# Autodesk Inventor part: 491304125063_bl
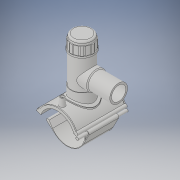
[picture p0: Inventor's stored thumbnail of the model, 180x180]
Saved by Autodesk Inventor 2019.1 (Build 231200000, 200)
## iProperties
Created: 2017-07
Part Number: 491304125063_bl
Material: Generic
Description: PLASSON TAPPING TEE SADDLE 125mm x 63mm
Document SubType Name: Modeling
Designer: KIM
Mass: 1712.7 g
Surface Area: 2671.49 cm^2
Volume: 1712.7 cm^3
Density: 1 g/cm^3
Appearance: Default
Author: KIM
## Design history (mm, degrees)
derived "491304.ipt"
feature "Solid1::491304.ipt" dims "ScaleForDerivedMember" = 10
feature "Solid2::491304.ipt" dims "ScaleForDerivedMember" = 10
feature "Solid4::491304.ipt" dims "ScaleForDerivedMember" = 10
feature "Solid5::491304.ipt" dims "ScaleForDerivedMember" = 10
tag "TaggingFeature1"
body "Solid1"
body "Solid2"
other parameters: "d0" = 125 [user parameter], "d1" = 101.118 [user parameter], "d2" = 264 [user parameter], "d3" = 31.25 [user parameter], "d4" = 176 [user parameter], "d5" = 0 [user parameter], "d6" = 0.1 [user parameter], "d8" = 0 [user parameter], "d40" = 75 [user parameter], "d41" = 97.65 [user parameter], "d43" = 0 [user parameter], "d45" = 0 [user parameter], "d47" = 156.159 [user parameter], "d78" = 97.5 [user parameter], "d79" = 15 [user parameter], "d80" = 70.4 [user parameter], "d82" = 5 deg [user parameter], "d84" = 4 [user parameter], "d85" = 14 [user parameter], "d86" = 0 [user parameter], "d87" = 3 [user parameter], "d88" = 0 [user parameter], "d97" = 3.52 [user parameter], "d98" = 0 [user parameter], "d102" = 1.25 [user parameter], "d120" = 140 deg [user parameter], "d123" = 606.708 [user parameter], "d126" = 0 [user parameter], "d153" = 176 [user parameter], "d154" = 0 [user parameter], "d159" = -4.7764 [user parameter], "d162" = 105.6 [user parameter], "d163" = 0 [user parameter], "d164" = 62.5 [user parameter], "d169" = 4.0905 [user parameter], "d172" = 0 [user parameter], "d173" = 1 [user parameter], "d175" = 62.5 [user parameter], "d176" = 20 deg [user parameter], "d177" = 8.75 [user parameter], "d180" = 0 [user parameter], "d184" = 7 [user parameter], "d187" = 68.75 [user parameter], "d188" = 15 [user parameter], "d189" = 8.75 [user parameter], "d190" = 0 [user parameter], "d191" = 93.75 [user parameter], "d195" = 90 deg [user parameter], "d197" = 0 [user parameter], "d199" = 0 [user parameter], "d200" = 8.75 [user parameter], "d202" = 0 [user parameter], "d203" = 195 [user parameter], "d206" = 75.6 [user parameter], "d207" = 146.25 [user parameter], "d208" = 152.1 [user parameter], "d209" = 181.35 [user parameter], "d210" = 76.86 [user parameter], "d212" = 72.45 [user parameter], "d213" = 39.15 [user parameter], "d216" = 0 [user parameter], "d217" = 12.5 [user parameter], "d218" = 6.25 [user parameter], "d219" = 1.25 [user parameter], "d222" = 125 [user parameter], "d224" = 0 [user parameter], "d259" = 50.4 [user parameter], "d260" = 63 [user parameter], "d263" = 165 [user parameter], "d265" = 0 [user parameter], "d267" = 13.00006 [user parameter], "d268" = 2.60001 [user parameter], "d269" = 2.60001 [user parameter], "d271" = 2.60001 [user parameter], "d273" = 0 [user parameter], "d274" = 23.56194 [user parameter], "d280" = 0 [user parameter], "d281" = 125 [user parameter], "d283" = 0 [user parameter], "d285" = 0 [user parameter], "d290" = 12.5 [user parameter], "d293" = 68.75 [user parameter], "d294" = 64.375 [user parameter], "d296" = 18.75 [user parameter], "d299" = 75 [user parameter], "d300" = 3 [user parameter], "d301" = 5 [user parameter], "d303" = 81.9 [user parameter], "d304" = 69.3 [user parameter], "d305" = 45 deg [user parameter], "d306" = 50.4 [user parameter], "d307" = 78.125 [user parameter], "d308" = 75 [user parameter], "d309" = 625 [user parameter], "d310" = 1 [user parameter], "d314" = 375 [user parameter], "d" = 125 [user parameter], "B" = 165 [user parameter], "L" = 176 [user parameter], "d_t" = 6 [user parameter], "H2" = 195 [user parameter], "H1" = 75 [user parameter], "d_1" = 63 [user parameter]
